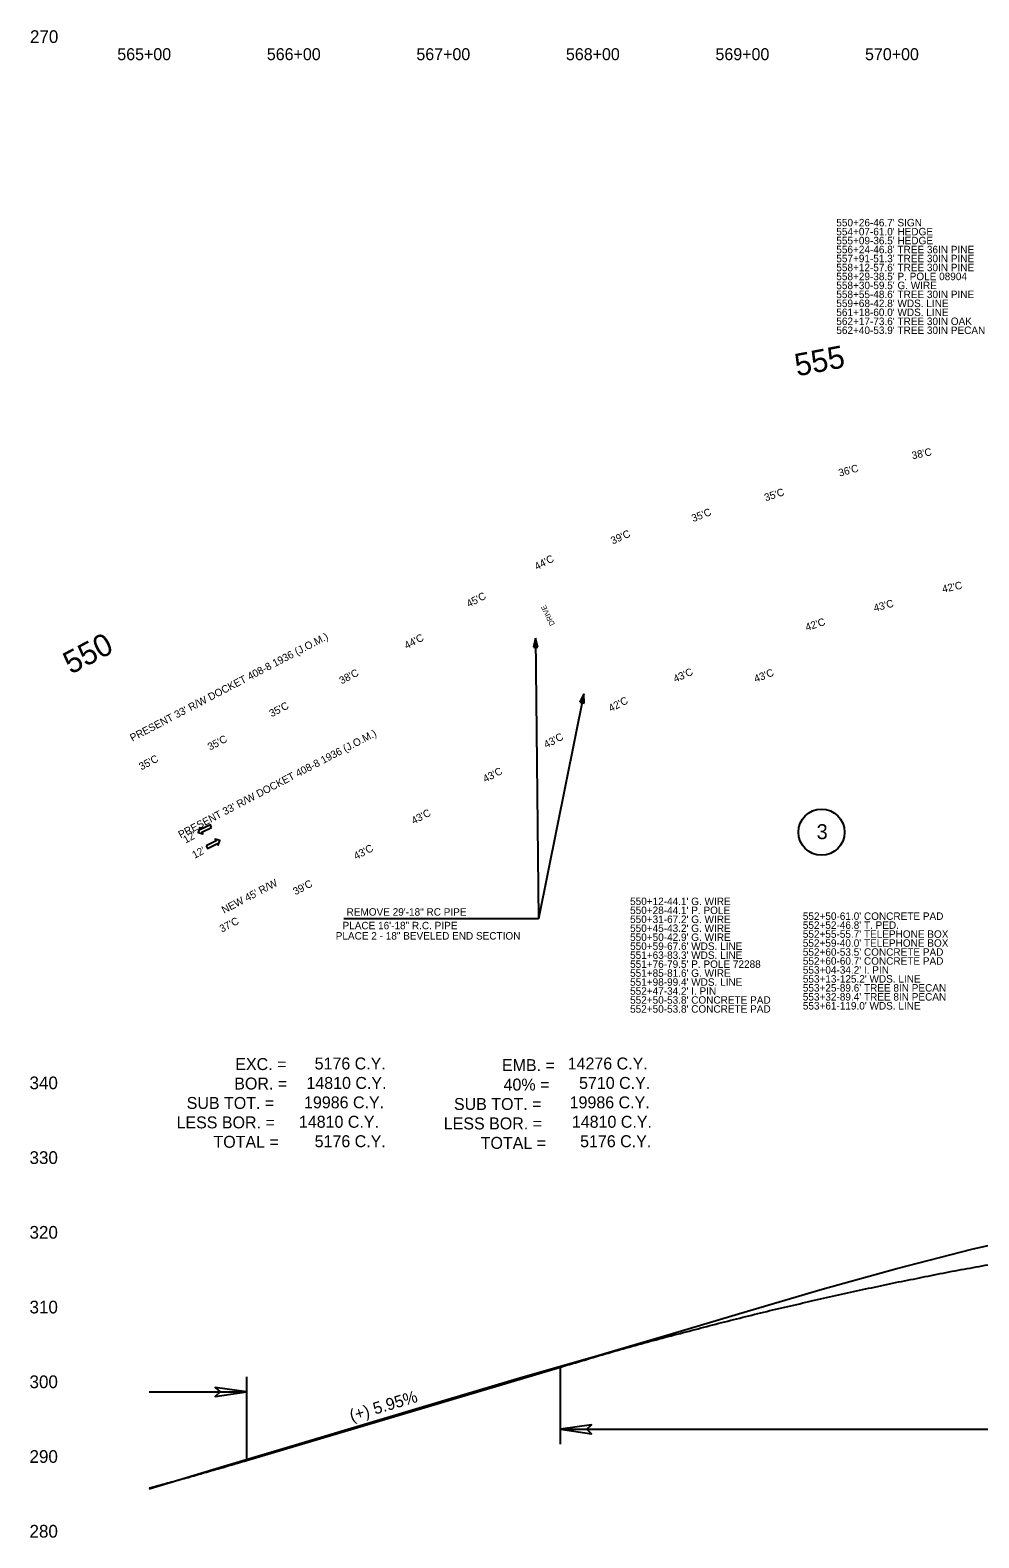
# Model space of a CAD drawing. Extents: x 48556 to 51363, y 45290 to 53458.
# Drawn here: x 49108 to 49743, y 51425 to 52434 of the extents above; entities that cross this region are included whole.
import ezdxf

# ---------------------------------------------------------------- set-up
doc = ezdxf.new("R2010")
doc.units = 0
for name, color, linetype in [('Level 1', 7, 'Continuous'), ('Level 12', 7, 'Continuous'), ('Level 14', 7, 'Continuous'), ('Level 19', 7, 'Continuous'), ('Level 20', 7, 'Continuous'), ('Level 24', 7, 'Continuous'), ('Level 29', 7, 'Continuous'), ('Level 33', 7, 'Continuous'), ('Level 40', 7, 'Continuous'), ('Level 41', 7, 'Continuous'), ('Level 42', 7, 'Continuous'), ('Level 45', 7, 'Continuous'), ('Level 48', 7, 'Continuous'), ('Level 6', 7, 'Continuous'), ('Level 8', 7, 'Continuous')]:
    doc.layers.add(name, color=color, linetype=linetype)

msp = doc.modelspace()

# ---------------------------------------------------------------- linework, layer by layer
at = {"layer": 'Level 1'}
for points in [[(49252.9, 51522.9), (49232.1, 51525.8), (49235.3, 51522.9), (49232.1, 51519.9)], [(49462.9, 51497.9), (49483.7, 51494.9), (49480.5, 51497.9), (49483.7, 51500.8)]]:
    msp.add_lwpolyline(points, close=True, dxfattribs=at)
at = {"layer": 'Level 12'}
msp.add_circle((49637.5, 51897.4), 15.4, dxfattribs=at)
at = {"layer": 'Level 14'}
for points in [[(49229.7, 51900.6), (49228.9, 51902.3), (49222.3, 51899.1), (49221.7, 51900.2), (49220.7, 51897.2), (49223.8, 51896.2), (49223.2, 51897.4)], [(49226.1, 51888.3), (49226.9, 51886.5), (49233.5, 51889.8), (49234.1, 51888.7), (49235.1, 51891.7), (49232.1, 51892.7), (49232.7, 51891.5)]]:
    msp.add_lwpolyline(points, close=True, dxfattribs=at)
at = {"layer": 'Level 24'}
for p, q in [((49446.2, 52027.1), (49444.8, 52021.1)), ((49447.8, 52021.1), (49446.2, 52027.1)), ((49444.8, 52021.1), (49447.8, 52021.1)), ((49478.5, 51989.9), (49475.8, 51984.3)), ((49475.8, 51984.3), (49478.8, 51983.7)), ((49478.8, 51983.7), (49478.5, 51989.9))]:
    msp.add_line(p, q, dxfattribs=at)
at = {"layer": 'Level 40'}
msp.add_lwpolyline([(49187.9, 51458.1), (49237.9, 51473.2), (49287.9, 51488.2), (49337.9, 51503.1), (49387.9, 51518), (49437.9, 51532.9), (49487.9, 51547.3), (49537.9, 51562), (49587.9, 51577), (49637.9, 51591.6), (49687.9, 51605.5), (49737.9, 51618.4), (49787.9, 51629.6)], dxfattribs=at)
at = {"layer": 'Level 41'}
for p, q in [((49462.9, 51487.9), (49462.9, 51539.5)), ((49252.9, 51532.9), (49252.9, 51477)), ((49187.9, 51522.9), (49252.9, 51522.9)), ((49462.9, 51497.9), (50262.9, 51497.9))]:
    msp.add_line(p, q, dxfattribs=at)
at = {"layer": 'Level 45'}
msp.add_line((49252.9, 51477), (49462.9, 51539.5), dxfattribs=at)
for points in [[(49462.9, 51539.5), (49478.9, 51544.2), (49494.9, 51548.9), (49510.9, 51553.4), (49526.9, 51557.8), (49542.9, 51562), (49558.9, 51566.2), (49574.9, 51570.3), (49590.9, 51574.3), (49606.9, 51578.2), (49622.9, 51581.9), (49638.9, 51585.6), (49654.9, 51589.2), (49670.9, 51592.6), (49686.9, 51596), (49702.9, 51599.2), (49718.9, 51602.4), (49734.9, 51605.4), (49750.9, 51608.3), (49766.9, 51611.2), (49782.9, 51613.9), (49798.9, 51616.5), (49814.9, 51619), (49830.9, 51621.5), (49846.9, 51623.8), (49862.9, 51626), (49878.9, 51628.1), (49894.9, 51630.1), (49910.9, 51632), (49926.9, 51633.7), (49942.9, 51635.4), (49958.9, 51637), (49974.9, 51638.5), (49990.9, 51639.8), (50006.9, 51641.1), (50022.9, 51642.3), (50038.9, 51643.3), (50054.9, 51644.3), (50070.9, 51645.1), (50086.9, 51645.9), (50102.9, 51646.5), (50118.9, 51647), (50134.9, 51647.5), (50150.9, 51647.8), (50166.9, 51648), (50182.9, 51648.1), (50198.9, 51648.1), (50214.9, 51648), (50230.9, 51647.8), (50246.9, 51647.5), (50262.9, 51647.1)], [(49187.9, 51458.6), (49189.2, 51458.9), (49190.5, 51459.3), (49191.8, 51459.6), (49193.1, 51460), (49194.4, 51460.3), (49195.7, 51460.7), (49197, 51461.1), (49198.3, 51461.4), (49199.6, 51461.8), (49200.9, 51462.1), (49202.2, 51462.5), (49203.5, 51462.8), (49204.8, 51463.2), (49206.1, 51463.6), (49207.4, 51463.9), (49208.7, 51464.3), (49210, 51464.7), (49211.3, 51465), (49212.6, 51465.4), (49213.9, 51465.7), (49215.2, 51466.1), (49216.5, 51466.5), (49217.8, 51466.8), (49219.1, 51467.2), (49220.4, 51467.6), (49221.7, 51468), (49223, 51468.3), (49224.3, 51468.7), (49225.6, 51469.1), (49226.9, 51469.4), (49228.2, 51469.8), (49229.5, 51470.2), (49230.8, 51470.6), (49232.1, 51470.9), (49233.4, 51471.3), (49234.7, 51471.7), (49236, 51472.1), (49237.3, 51472.4), (49238.6, 51472.8), (49239.9, 51473.2), (49241.2, 51473.6), (49242.5, 51474), (49243.8, 51474.3), (49245.1, 51474.7), (49246.4, 51475.1), (49247.7, 51475.5), (49249, 51475.9), (49250.3, 51476.3), (49251.6, 51476.6), (49252.9, 51477)]]:
    msp.add_spline(points, degree=3, dxfattribs=at)
at = {"layer": 'Level 6'}
for p, q in [((49446.2, 52027.1), (49448.2, 51839.5)), ((49478.5, 51989.9), (49448.2, 51839.5)), ((49448.2, 51839.5), (49318.1, 51839.5))]:
    msp.add_line(p, q, dxfattribs=at)

# ---------------------------------------------------------------- texts
at = {"layer": 'Level 1'}
for p in [(49176.7, 51957.9), (49209, 51893.1)]:
    msp.add_text("PRESENT 33' R/W DOCKET 408-8 1936 (J.O.M.)", height=5, rotation=27.6333, dxfattribs=at).set_placement(p)
for s, p in [('EXC. =', (49245.5, 51738.2)), (' 5176 C.Y.', (49295.6, 51738.6)), ('EMB. =', (49423.8, 51737.5)), (' 14276 C.Y.', (49464.8, 51738.6)), ('BOR. =', (49244.8, 51725.2)), (' 14810 C.Y.', (49290.1, 51725.6)), ('40% =', (49424.9, 51724.5)), (' 5710 C.Y.', (49472.4, 51725.6)), ('SUB TOT. =', (49213, 51712.2)), (' 19986 C.Y.', (49288.5, 51712.6)), ('SUB TOT. =', (49391.7, 51711.5)), (' 19986 C.Y.', (49466.1, 51712.6)), ('LESS BOR. =', (49206.2, 51699.2)), ('  14810 C.Y.', (49282.1, 51699.6)), ('LESS BOR. =', (49384.9, 51698.5)), (' 14810 C.Y.', (49467.6, 51699.6)), ('TOTAL =', (49230.9, 51686.2)), (' 5176 C.Y.', (49295.6, 51686.6)), ('TOTAL =', (49409.6, 51685.5)), (' 5176 C.Y.', (49473.1, 51686.6))]:
    msp.add_text(s, height=8, dxfattribs=at).set_placement(p)
at = {"layer": 'Level 12'}
msp.add_text('3', height=10, dxfattribs=at).set_placement((49634.2, 51892.7))
at = {"layer": 'Level 19'}
for s, rotation, p in [('555', 10.8035, (49621.1, 52202.3)), ('550', 27.6333, (49135.5, 52002.7))]:
    msp.add_text(s, height=15, rotation=rotation, dxfattribs=at).set_placement(p)
at = {"layer": 'Level 20'}
for p in [(49212.3, 51889.7), (49218.3, 51879.5)]:
    msp.add_text("12'", height=5, rotation=28.5393, dxfattribs=at).set_placement(p)
at = {"layer": 'Level 24'}
for s, p in [("550+26-46.7' SIGN", (49647.4, 52302.7)), ("554+07-61.0' HEDGE", (49647.4, 52296.7)), ("555+09-36.5' HEDGE", (49647.4, 52290.7)), ("556+24-46.8' TREE 36IN PINE", (49647.4, 52284.7)), ("557+91-51.3' TREE 30IN PINE", (49647.4, 52278.7)), ("558+12-57.6' TREE 30IN PINE", (49647.4, 52272.7)), ("558+29-38.5' P. POLE 08904", (49647.4, 52266.7)), ("558+30-59.5' G. WIRE", (49647.4, 52260.7)), ("558+55-48.6' TREE 30IN PINE", (49647.4, 52254.7)), ("559+68-42.8' WDS. LINE", (49647.4, 52248.7)), ("561+18-60.0' WDS. LINE", (49647.4, 52242.7)), ("562+17-73.6' TREE 30IN OAK", (49647.4, 52236.7)), ("562+40-53.9' TREE 30IN PECAN", (49647.4, 52230.7)), ("550+12-44.1' G. WIRE", (49509.5, 51848.6)), ("550+28-44.1' P. POLE", (49509.5, 51842.6)), ("550+31-67.2' G. WIRE", (49509.5, 51836.6)), ("552+50-61.0' CONCRETE PAD", (49625, 51838.7)), ("550+45-43.2' G. WIRE", (49509.5, 51830.6)), ("550+50-42.9' G. WIRE", (49509.5, 51824.6)), ("552+52-46.8' T. PED.", (49625, 51832.7)), ("552+55-55.7' TELEPHONE BOX", (49625, 51826.7)), ("550+59-67.6' WDS. LINE", (49509.5, 51818.6)), ("552+59-40.0' TELEPHONE BOX", (49625, 51820.7)), ("552+60-53.5' CONCRETE PAD", (49625, 51814.7)), ("551+63-83.3' WDS. LINE", (49509.5, 51812.6)), ("551+76-79.5' P. POLE 72288", (49509.5, 51806.6)), ("552+60-60.7' CONCRETE PAD", (49625, 51808.7)), ("551+85-81.6' G. WIRE", (49509.5, 51800.6)), ("551+98-99.4' WDS. LINE", (49509.5, 51794.6)), ("553+04-34.2' I. PIN", (49625, 51802.7)), ("553+13-125.2' WDS. LINE", (49625, 51796.7)), ("552+47-34.2' I. PIN", (49509.5, 51788.6)), ("553+25-89.6' TREE 8IN PECAN", (49625, 51790.7)), ("553+32-89.4' TREE 8IN PECAN", (49625, 51784.7)), ("552+50-53.8' CONCRETE PAD", (49509.5, 51782.6)), ("552+50-53.8' CONCRETE PAD", (49509.5, 51776.6)), ("553+61-119.0' WDS. LINE", (49625, 51778.7))]:
    msp.add_text(s, height=5, dxfattribs=at).set_placement(p)
at = {"layer": 'Level 29'}
for s, p in [(' PLACE 2 - 18" BEVELED END SECTION', (49310.8, 51825.5)), ('PLACE 16\'-18" R.C. PIPE', (49317.2, 51832.4))]:
    msp.add_text(s, height=5, dxfattribs=at).set_placement(p)
at = {"layer": 'Level 33'}
msp.add_text("NEW 45' R/W", height=5, rotation=27.8257, dxfattribs=at).set_placement((49238, 51842.7))
at = {"layer": 'Level 41'}
msp.add_text('(+) 5.95%', height=8, rotation=16.576, dxfattribs=at).set_placement((49323.3, 51503))
at = {"layer": 'Level 42'}
for s, height, p in [('270', 8.5, (49108.2, 52425.4)), ('565+00', 8, (49166.6, 52413.9)), ('566+00', 8, (49266.6, 52413.9)), ('567+00', 8, (49366.6, 52413.9)), ('568+00', 8, (49466.6, 52413.9)), ('569+00', 8, (49566.6, 52413.9)), ('570+00', 8, (49666.6, 52413.9)), ('340', 8.5, (49107.9, 51725.4)), ('330', 8.5, (49107.9, 51675.4)), ('320', 8.5, (49107.9, 51625.4)), ('310', 8.5, (49107.9, 51575.4)), ('300', 8.5, (49107.9, 51525.4)), ('290', 8.5, (49107.9, 51475.4)), ('280', 8.5, (49107.9, 51425.4))]:
    msp.add_text(s, height=height, dxfattribs=at).set_placement(p)
at = {"layer": 'Level 48'}
for s, rotation, p in [("38'C", 12.2965, (49698.4, 52146.8)), ("36'C", 15.2652, (49649.6, 52135.2)), ("35'C", 18.2339, (49600.2, 52118.7)), ("35'C", 21.2026, (49551.7, 52104.8)), ("39'C", 24.1713, (49497.9, 52089.8)), ("44'C", 27.14, (49447.1, 52072.6)), ("42'C", 12.2965, (49718.7, 52057.5)), ("45'C", 27.6334, (49401.7, 52047.6)), ("43'C", 15.2652, (49673.1, 52044.8)), ("42'C", 18.2339, (49627.6, 52031.9)), ("44'C", 27.6334, (49360.1, 52019.7)), ("38'C", 27.6334, (49316.6, 51996.2)), ("43'C", 24.1713, (49539.7, 51997.4)), ("43'C", 21.2026, (49593.5, 51997.4)), ("35'C", 27.6334, (49269.8, 51974.2)), ("42'C", 27.14, (49496.6, 51977.7)), ("35'C", 27.6333, (49228.6, 51951.9)), ("43'C", 27.6334, (49453.4, 51953.4)), ("35'C", 27.6334, (49182.7, 51938.7)), ("43'C", 27.6334, (49412.7, 51930.4)), ("43'C", 27.6334, (49364.8, 51902.5)), ("43'C", 27.6334, (49326.3, 51878.8)), ("39'C", 27.6334, (49285.7, 51855.1)), ("37'C", 27.6334, (49236.5, 51830.1))]:
    msp.add_text(s, height=5, rotation=rotation, dxfattribs=at).set_placement(p)
at = {"layer": 'Level 6'}
msp.add_text('REMOVE 29\'-18" RC PIPE', height=5, dxfattribs=at).set_placement((49319.9, 51841.5))
at = {"layer": 'Level 8'}
msp.add_text('DRIVE', height=3.5, rotation=115.7387, dxfattribs=at).set_placement((49459.3, 52036.5))

doc.saveas('drawing.dxf')
